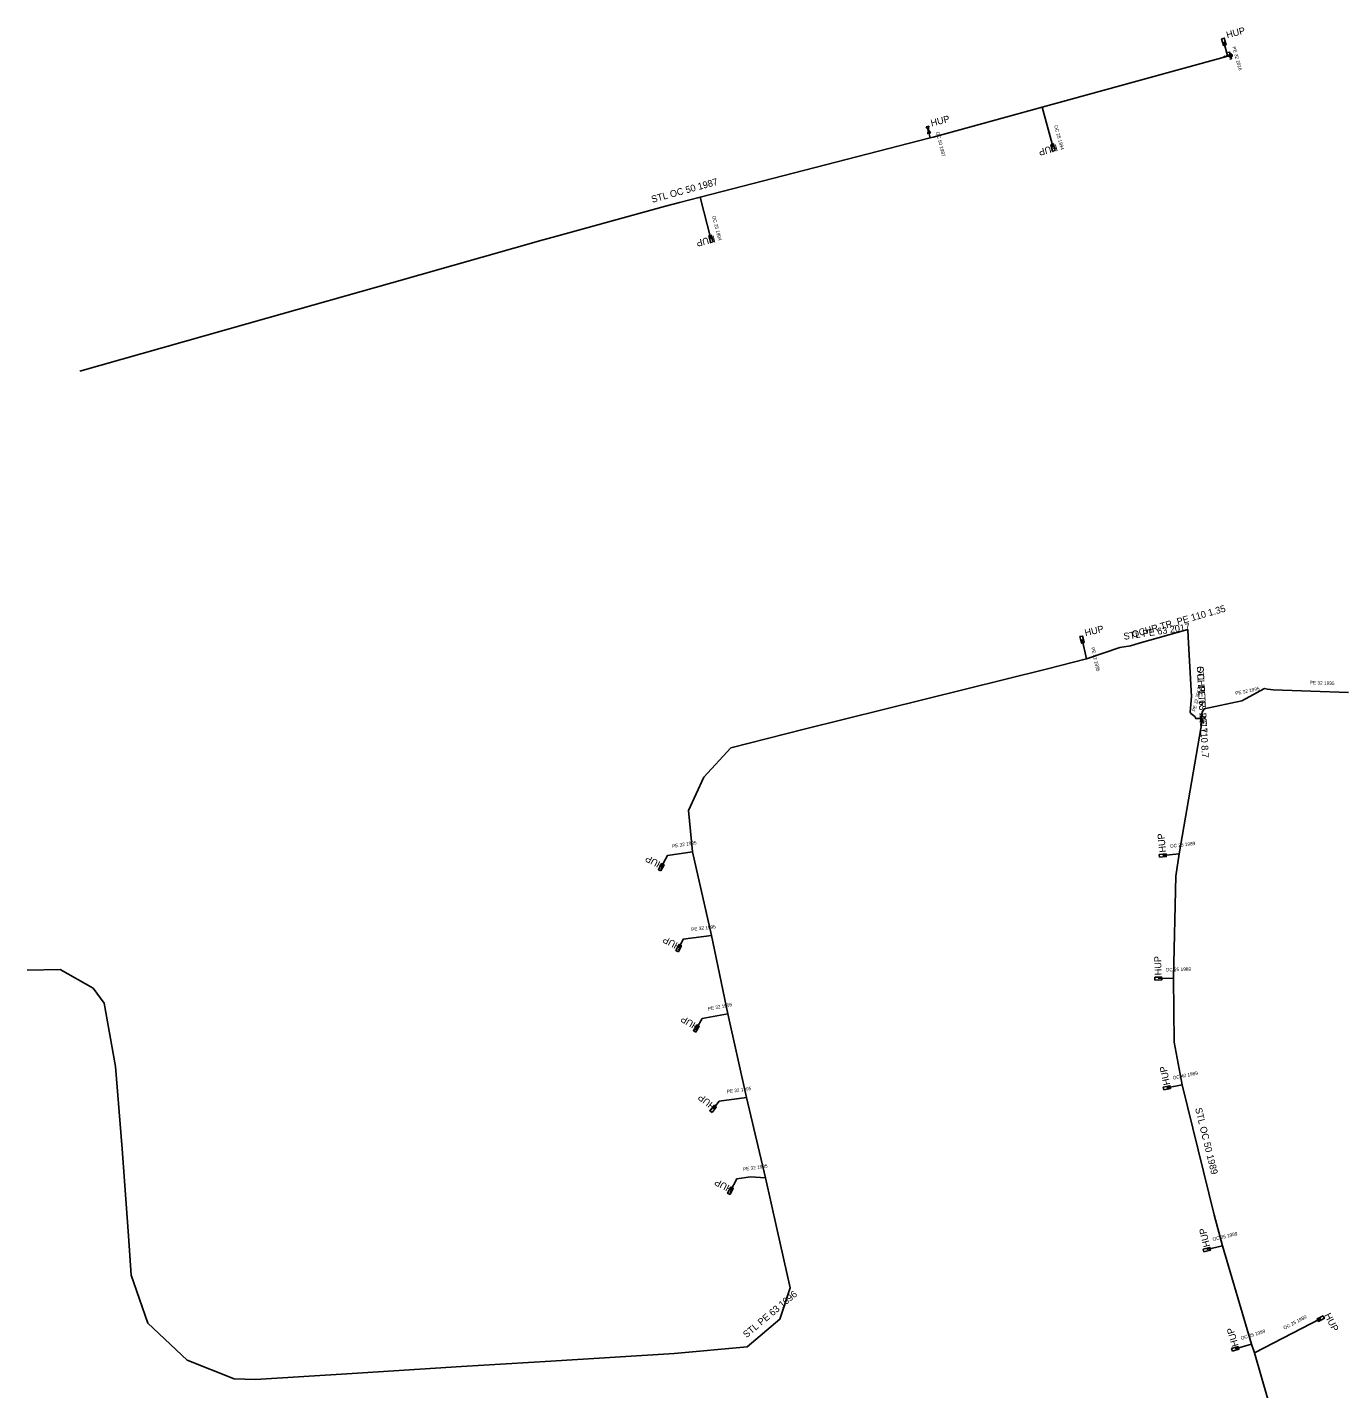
# Model space of a CAD drawing. Extents: x -734239 to -733693, y -1053757 to -1053379.
# Drawn here: x -734238.9 to -734046.3, y -1053596.5 to -1053397.2 of the extents above; entities that cross this region are included whole.
import ezdxf

# ---------------------------------------------------------------- set-up
doc = ezdxf.new("R2010")
doc.units = 0
for name, color, linetype in [('ST OP Chráni_ka - provoz', 7, 'Continuous'), ('ST Úsek p_ípojky - provoz', 7, 'Continuous'), ('ST Úsek plynovodu - provoz', 7, 'Continuous'), ('ST_HUP_22_23_popis', 7, 'Continuous'), ('ST_HUP_24_popis', 7, 'Continuous'), ('Vrstva 1', 7, 'Continuous')]:
    doc.layers.add(name, color=color, linetype=linetype)

msp = doc.modelspace()

# ---------------------------------------------------------------- linework, layer by layer
at = {"layer": 'ST OP Chráni_ka - provoz'}
for points in [[(-734068.82, -1053486.47), (-734068.32, -1053495.16)], [(-734077.29, -1053487.74), (-734075.99, -1053487.37)], [(-734068.42, -1053497.65), (-734067.87, -1053498.09)]]:
    msp.add_lwpolyline(points, dxfattribs=at)
at = {"layer": 'ST Úsek p_ípojky - provoz'}
for points in [[(-734063.05, -1053401.34), (-734063.61, -1053399.29)], [(-734063.03, -1053401.41), (-734063.05, -1053401.34)], [(-734090.24, -1053408.87), (-734088.61, -1053414.79)], [(-734106.61, -1053413.35), (-734106.91, -1053412.2)], [(-734140.32, -1053422.03), (-734138.74, -1053428.16)], [(-734083.7, -1053489.64), (-734084.37, -1053486.84)], [(-734066.49, -1053496.98), (-734060.98, -1053495.8), (-734057.64, -1053494.01), (-734057.2, -1053494.07)], [(-734057.2, -1053494.07), (-734056.77, -1053494.13)], [(-734056.77, -1053494.13), (-734056.37, -1053494.18), (-734045.32, -1053494.56)], [(-734066.99, -1053498.37), (-734066.77, -1053497.48), (-734066.49, -1053496.98)], [(-734141.43, -1053517.89), (-734145.12, -1053518.45), (-734146.02, -1053520.18)], [(-734070.16, -1053518.19), (-734072.55, -1053518.46)], [(-734138.66, -1053530.18), (-734142.79, -1053530.68), (-734143.46, -1053532.02)], [(-734070.96, -1053536.4), (-734073.21, -1053536.48)], [(-734136.26, -1053541.64), (-734140.01, -1053542.34), (-734140.87, -1053543.79)], [(-734069.71, -1053552.02), (-734071.95, -1053552.48)], [(-734133.54, -1053553.9), (-734137.53, -1053554.44), (-734138.43, -1053555.56)], [(-734130.76, -1053565.66), (-734132.96, -1053565.51), (-734134.96, -1053565.8), (-734135.88, -1053567.56)], [(-734063.82, -1053575.62), (-734066.09, -1053576.17)], [(-734059.12, -1053591.3), (-734049.4, -1053586.26)], [(-734059.57, -1053589.99), (-734061.93, -1053590.7)]]:
    msp.add_lwpolyline(points, dxfattribs=at)
at = {"layer": 'ST Úsek plynovodu - provoz'}
for points in [[(-734231.18, -1053447.52), (-734203.79, -1053439.77), (-734185.5, -1053434.59), (-734163.32, -1053428.31), (-734163.11, -1053428.25), (-734161.49, -1053427.8), (-734145.37, -1053423.37), (-734143.32, -1053422.8), (-734140.32, -1053422.03), (-734106.61, -1053413.35), (-734106.19, -1053413.25), (-734090.24, -1053408.87), (-734063.03, -1053401.41), (-734062.62, -1053401.3)], [(-734075.99, -1053487.37), (-734068.88, -1053485.36), (-734068.82, -1053486.47)], [(-734068.82, -1053486.47), (-734068.32, -1053495.16)], [(-734238.89, -1053535.26), (-734234.07, -1053535.13), (-734229.21, -1053537.88), (-734227.6, -1053540.06), (-734225.96, -1053549.36), (-734224.97, -1053561.43), (-734224.06, -1053574.14), (-734223.68, -1053579.89), (-734221.23, -1053586.92), (-734215.45, -1053592.34), (-734208.58, -1053595.07), (-734205.45, -1053595.21), (-734191.29, -1053594.3), (-734175.28, -1053593.27), (-734162.21, -1053592.51), (-734144.14, -1053591.38), (-734133.45, -1053590.39), (-734128.65, -1053586.37), (-734127.12, -1053581.78), (-734129.09, -1053573.05), (-734130.76, -1053565.66), (-734133.54, -1053553.9), (-734136.26, -1053541.64), (-734138.66, -1053530.18), (-734141.43, -1053517.89), (-734142.01, -1053511.85), (-734139.79, -1053507), (-734135.81, -1053502.7), (-734125.1, -1053499.96), (-734107.35, -1053495.55), (-734089.65, -1053491.15), (-734083.7, -1053489.64), (-734078.83, -1053487.97)], [(-734078.83, -1053487.97), (-734077.29, -1053487.74)], [(-734077.29, -1053487.74), (-734075.99, -1053487.37)], [(-734068.32, -1053495.16), (-734068.54, -1053497.48), (-734068.42, -1053497.65)], [(-734066.74, -1053498.42), (-734070.16, -1053518.19), (-734070.63, -1053521.47), (-734070.96, -1053536.4), (-734070.88, -1053545.79), (-734069.71, -1053552.02), (-734065.01, -1053571.09), (-734063.82, -1053575.62), (-734059.57, -1053589.99), (-734059.12, -1053591.3), (-734055.28, -1053604.51), (-734053.25, -1053611.48)], [(-734068.42, -1053497.65), (-734067.87, -1053498.09)], [(-734067.87, -1053498.09), (-734067.71, -1053498.39), (-734066.99, -1053498.37), (-734066.91, -1053498.39)], [(-734066.91, -1053498.39), (-734066.74, -1053498.42)]]:
    msp.add_lwpolyline(points, dxfattribs=at)
at = {"layer": 'Vrstva 1'}
for p, q in [((-734063.53, -1053401.48), (-734063.57, -1053401.33)), ((-734063.53, -1053401.48), (-734062.56, -1053401.21)), ((-734062.49, -1053401.78), (-734062.62, -1053401.3)), ((-734062.56, -1053401.21), (-734062.53, -1053401.36)), ((-734067, -1053498.88), (-734067.14, -1053498.86)), ((-734066.82, -1053497.9), (-734067, -1053498.88)), ((-734066.82, -1053497.9), (-734066.68, -1053497.92))]:
    msp.add_line(p, q, dxfattribs=at)
for points in [[(-734063.93, -1053398.86), (-734063.54, -1053398.75), (-734063.28, -1053399.72), (-734063.67, -1053399.82)], [(-734062.55, -1053401.54), (-734062.57, -1053401.55), (-734062.59, -1053401.55), (-734062.62, -1053401.55), (-734062.64, -1053401.55), (-734062.67, -1053401.55), (-734062.69, -1053401.54), (-734062.71, -1053401.54), (-734062.74, -1053401.53), (-734062.76, -1053401.51), (-734062.78, -1053401.5), (-734062.8, -1053401.48), (-734062.81, -1053401.47), (-734062.83, -1053401.45), (-734062.84, -1053401.43), (-734062.85, -1053401.4), (-734062.86, -1053401.38), (-734062.87, -1053401.36), (-734062.87, -1053401.33), (-734062.88, -1053401.31), (-734062.87, -1053401.28), (-734062.87, -1053401.26), (-734062.87, -1053401.24), (-734062.86, -1053401.21), (-734062.85, -1053401.19), (-734062.84, -1053401.17), (-734062.82, -1053401.15), (-734062.81, -1053401.13), (-734062.79, -1053401.11), (-734062.77, -1053401.1), (-734062.75, -1053401.08), (-734062.73, -1053401.07), (-734062.7, -1053401.06), (-734062.68, -1053401.06), (-734062.66, -1053401.05), (-734062.63, -1053401.05), (-734062.61, -1053401.05), (-734062.58, -1053401.06), (-734062.56, -1053401.06), (-734062.54, -1053401.07), (-734062.51, -1053401.08), (-734062.49, -1053401.09), (-734062.47, -1053401.1), (-734062.45, -1053401.12), (-734062.44, -1053401.14), (-734062.42, -1053401.16), (-734062.41, -1053401.18), (-734062.4, -1053401.2), (-734062.39, -1053401.22), (-734062.38, -1053401.25), (-734062.38, -1053401.27), (-734062.37, -1053401.29), (-734062.38, -1053401.32), (-734062.38, -1053401.34), (-734062.38, -1053401.37), (-734062.39, -1053401.39), (-734062.4, -1053401.41), (-734062.41, -1053401.43), (-734062.43, -1053401.46), (-734062.44, -1053401.47), (-734062.46, -1053401.49), (-734062.48, -1053401.51), (-734062.5, -1053401.52), (-734062.52, -1053401.53)], [(-734062.46, -1053401.25), (-734062.45, -1053401.26), (-734062.45, -1053401.28), (-734062.45, -1053401.3), (-734062.45, -1053401.31), (-734062.45, -1053401.33), (-734062.46, -1053401.35), (-734062.46, -1053401.36), (-734062.47, -1053401.38), (-734062.48, -1053401.4), (-734062.49, -1053401.41), (-734062.5, -1053401.42), (-734062.51, -1053401.43), (-734062.52, -1053401.44), (-734062.54, -1053401.45), (-734062.55, -1053401.46), (-734062.57, -1053401.47), (-734062.59, -1053401.47), (-734062.6, -1053401.48), (-734062.62, -1053401.48), (-734062.64, -1053401.48), (-734062.65, -1053401.47), (-734062.67, -1053401.47), (-734062.69, -1053401.47), (-734062.7, -1053401.46), (-734062.72, -1053401.45), (-734062.73, -1053401.44), (-734062.74, -1053401.43), (-734062.76, -1053401.42), (-734062.77, -1053401.4), (-734062.78, -1053401.39), (-734062.78, -1053401.37), (-734062.79, -1053401.36), (-734062.8, -1053401.34), (-734062.8, -1053401.32), (-734062.8, -1053401.31), (-734062.8, -1053401.29), (-734062.8, -1053401.27), (-734062.79, -1053401.26), (-734062.79, -1053401.24), (-734062.78, -1053401.22), (-734062.77, -1053401.21), (-734062.76, -1053401.19), (-734062.75, -1053401.18), (-734062.74, -1053401.17), (-734062.73, -1053401.16), (-734062.71, -1053401.15), (-734062.7, -1053401.14), (-734062.68, -1053401.14), (-734062.66, -1053401.13), (-734062.65, -1053401.13), (-734062.63, -1053401.13), (-734062.61, -1053401.13), (-734062.6, -1053401.13), (-734062.58, -1053401.13), (-734062.56, -1053401.14), (-734062.55, -1053401.14), (-734062.53, -1053401.15), (-734062.52, -1053401.16), (-734062.51, -1053401.17), (-734062.49, -1053401.19), (-734062.48, -1053401.2), (-734062.47, -1053401.21), (-734062.46, -1053401.23)], [(-734062.77, -1053401.35), (-734062.77, -1053401.34), (-734062.77, -1053401.32), (-734062.78, -1053401.31), (-734062.77, -1053401.29), (-734062.77, -1053401.28), (-734062.77, -1053401.26), (-734062.76, -1053401.25), (-734062.76, -1053401.23), (-734062.75, -1053401.22), (-734062.74, -1053401.21), (-734062.73, -1053401.2), (-734062.72, -1053401.19), (-734062.71, -1053401.18), (-734062.7, -1053401.17), (-734062.69, -1053401.16), (-734062.67, -1053401.16), (-734062.66, -1053401.16), (-734062.64, -1053401.15), (-734062.63, -1053401.15), (-734062.61, -1053401.15), (-734062.6, -1053401.15), (-734062.59, -1053401.16), (-734062.57, -1053401.16), (-734062.56, -1053401.17), (-734062.54, -1053401.17), (-734062.53, -1053401.18), (-734062.52, -1053401.19), (-734062.51, -1053401.2), (-734062.5, -1053401.21), (-734062.49, -1053401.23), (-734062.49, -1053401.24), (-734062.48, -1053401.25), (-734062.48, -1053401.27), (-734062.48, -1053401.28), (-734062.47, -1053401.3), (-734062.47, -1053401.31), (-734062.48, -1053401.33), (-734062.48, -1053401.34), (-734062.48, -1053401.35), (-734062.49, -1053401.37), (-734062.5, -1053401.38), (-734062.51, -1053401.39), (-734062.52, -1053401.41), (-734062.53, -1053401.42), (-734062.54, -1053401.42), (-734062.55, -1053401.43), (-734062.56, -1053401.44), (-734062.58, -1053401.44), (-734062.59, -1053401.45), (-734062.61, -1053401.45), (-734062.62, -1053401.45), (-734062.63, -1053401.45), (-734062.65, -1053401.45), (-734062.66, -1053401.45), (-734062.68, -1053401.44), (-734062.69, -1053401.44), (-734062.7, -1053401.43), (-734062.72, -1053401.42), (-734062.73, -1053401.41), (-734062.74, -1053401.4), (-734062.75, -1053401.39), (-734062.76, -1053401.38), (-734062.76, -1053401.36)], [(-734062.7, -1053401.33), (-734062.7, -1053401.32), (-734062.7, -1053401.31), (-734062.7, -1053401.3), (-734062.7, -1053401.3), (-734062.7, -1053401.29), (-734062.7, -1053401.28), (-734062.69, -1053401.27), (-734062.69, -1053401.27), (-734062.69, -1053401.26), (-734062.68, -1053401.26), (-734062.68, -1053401.25), (-734062.67, -1053401.25), (-734062.67, -1053401.24), (-734062.66, -1053401.24), (-734062.66, -1053401.23), (-734062.65, -1053401.23), (-734062.64, -1053401.23), (-734062.63, -1053401.23), (-734062.63, -1053401.23), (-734062.62, -1053401.23), (-734062.61, -1053401.23), (-734062.61, -1053401.23), (-734062.6, -1053401.23), (-734062.59, -1053401.23), (-734062.58, -1053401.24), (-734062.58, -1053401.24), (-734062.57, -1053401.25), (-734062.57, -1053401.25), (-734062.56, -1053401.26), (-734062.56, -1053401.26), (-734062.56, -1053401.27), (-734062.55, -1053401.28), (-734062.55, -1053401.28), (-734062.55, -1053401.29), (-734062.55, -1053401.3), (-734062.55, -1053401.31), (-734062.55, -1053401.31), (-734062.55, -1053401.32), (-734062.56, -1053401.33), (-734062.56, -1053401.34), (-734062.56, -1053401.34), (-734062.57, -1053401.35), (-734062.57, -1053401.35), (-734062.58, -1053401.36), (-734062.58, -1053401.36), (-734062.59, -1053401.37), (-734062.59, -1053401.37), (-734062.6, -1053401.37), (-734062.61, -1053401.38), (-734062.62, -1053401.38), (-734062.62, -1053401.38), (-734062.63, -1053401.38), (-734062.64, -1053401.38), (-734062.64, -1053401.37), (-734062.65, -1053401.37), (-734062.66, -1053401.37), (-734062.66, -1053401.37), (-734062.67, -1053401.36), (-734062.68, -1053401.36), (-734062.68, -1053401.35), (-734062.69, -1053401.35), (-734062.69, -1053401.34), (-734062.69, -1053401.33)], [(-734088.29, -1053415.22), (-734088.68, -1053415.32), (-734088.94, -1053414.36), (-734088.55, -1053414.25)], [(-734138.43, -1053428.6), (-734138.82, -1053428.69), (-734139.06, -1053427.72), (-734138.67, -1053427.63)], [(-734084.68, -1053486.4), (-734084.29, -1053486.31), (-734084.06, -1053487.28), (-734084.45, -1053487.37)], [(-734073.03, -1053518.71), (-734073.07, -1053518.31), (-734072.07, -1053518.21), (-734072.03, -1053518.61)], [(-734146.08, -1053520.71), (-734146.43, -1053520.53), (-734145.96, -1053519.64), (-734145.61, -1053519.83)], [(-734143.51, -1053532.55), (-734143.87, -1053532.37), (-734143.41, -1053531.48), (-734143.05, -1053531.66)], [(-734073.7, -1053536.69), (-734073.71, -1053536.29), (-734072.72, -1053536.26), (-734072.7, -1053536.66)], [(-734140.96, -1053544.32), (-734141.3, -1053544.12), (-734140.78, -1053543.26), (-734140.44, -1053543.46)], [(-734072.4, -1053552.78), (-734072.48, -1053552.39), (-734071.5, -1053552.18), (-734071.42, -1053552.57)], [(-734138.58, -1053556.07), (-734138.9, -1053555.82), (-734138.27, -1053555.04), (-734137.96, -1053555.29)], [(-734135.93, -1053568.09), (-734136.29, -1053567.91), (-734135.82, -1053567.02), (-734135.47, -1053567.21)], [(-734066.52, -1053576.48), (-734066.62, -1053576.09), (-734065.65, -1053575.85), (-734065.55, -1053576.24)], [(-734049.05, -1053585.85), (-734048.86, -1053586.21), (-734049.75, -1053586.67), (-734049.94, -1053586.31)], [(-734062.35, -1053591.03), (-734062.46, -1053590.65), (-734061.51, -1053590.36), (-734061.39, -1053590.75)]]:
    msp.add_lwpolyline(points, close=True, dxfattribs=at)
for points in [[(-734063, -1053400.88), (-734062.76, -1053400.82), (-734062.49, -1053401.78), (-734062.74, -1053401.85)], [(-734107.22, -1053411.76), (-734106.84, -1053411.66), (-734106.97, -1053412.73), (-734106.59, -1053412.63), (-734107.22, -1053411.76)]]:
    msp.add_lwpolyline(points, dxfattribs=at)

# ---------------------------------------------------------------- texts
at = {"layer": 'ST OP Chráni_ka - provoz'}
for s, rotation, p in [('OCHR.TR. PE 110 1.35', 15.8872, (-734076.91, -1053486.59)), ('OCHR.TR. PE 110 8.7', 273.293, (-734067.57, -1053490.76))]:
    msp.add_text(s, height=1, rotation=rotation, dxfattribs=at).set_placement(p)
at = {"layer": 'ST Úsek p_ípojky - provoz'}
for s, rotation, p in [('PE 32 2016', 285.2433, (-734062.36, -1053400.05)), ('OC 25 1994', 285.3411, (-734088.46, -1053411.57)), ('OC 50 1987', 284.3731, (-734105.79, -1053412.53)), ('OC 25 1994', 284.4446, (-734138.56, -1053424.84)), ('PE 32 1995', 283.4284, (-734083.06, -1053488.01)), ('PE 32 1995', 358.0358, (-734051.01, -1053493.36)), ('PE 32 2017', 76.1153, (-734067.78, -1053497.41)), ('PE 32 1995', 12.0877, (-734061.87, -1053494.97)), ('PE 32 1995', 8.6294, (-734144.39, -1053517.33)), ('OC 25 1989', 6.4244, (-734071.47, -1053517.33)), ('PE 32 1995', 6.9029, (-734141.59, -1053529.53)), ('OC 25 1989', 1.9618, (-734072.12, -1053535.44)), ('PE 32 1995', 10.5735, (-734139.15, -1053541.16)), ('OC 40 1989', 11.5557, (-734071.03, -1053551.27)), ('PE 32 1995', 7.7075, (-734136.38, -1053553.28)), ('PE 32 1995', 8.2504, (-734133.99, -1053564.65)), ('OC 25 1989', 13.5836, (-734065.19, -1053574.92)), ('OC 25 1989', 27.4076, (-734054.72, -1053587.89)), ('OC 25 1989', 16.7193, (-734061.04, -1053589.39))]:
    msp.add_text(s, height=0.5, rotation=rotation, dxfattribs=at).set_placement(p)
at = {"layer": 'ST Úsek plynovodu - provoz'}
for s, rotation, p in [('STL OC 50 1987', 15.3895, (-734147.32, -1053422.87)), ('STL PE 63 2017', 8.4944, (-734078.21, -1053486.87)), ('STL PE 63 2017', 273.293, (-734067.57, -1053490.76)), ('STL OC 50 1989', 283.8452, (-734067.82, -1053555.51)), ('STL PE 63 1996', 39.9462, (-734133.53, -1053589.15))]:
    msp.add_text(s, height=1, rotation=rotation, dxfattribs=at).set_placement(p)
at = {"layer": 'ST_HUP_22_23_popis'}
for rotation, p in [(14.97, (-734063.11, -1053398.79)), (195, (-734088.11, -1053414.29)), (194, (-734138.24, -1053427.66)), (13, (-734083.87, -1053486.34)), (96, (-734072.05, -1053517.96)), (152, (-734145.52, -1053519.68)), (153, (-734142.96, -1053531.52)), (92, (-734072.71, -1053535.98)), (149, (-734140.37, -1053543.29)), (102, (-734071.45, -1053551.98)), (141.28, (-734137.93, -1053555.06)), (152.39, (-734135.38, -1053567.06)), (104, (-734065.59, -1053575.67)), (297, (-734048.9, -1053585.76)), (106.72, (-734061.43, -1053590.2))]:
    msp.add_text('HUP', height=1, rotation=rotation, dxfattribs=at).set_placement(p)
at = {"layer": 'ST_HUP_24_popis'}
msp.add_text('HUP', height=1, rotation=14.37, dxfattribs=at).set_placement((-734106.41, -1053411.7))

doc.saveas('drawing.dxf')
